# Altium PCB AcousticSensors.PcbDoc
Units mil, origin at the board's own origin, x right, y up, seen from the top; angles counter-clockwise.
Board outline 6000 x 4000 mil, 2 copper layers (Top Layer, Bottom Layer); 17 components, 11 nets, 41 pads, 10 vias.
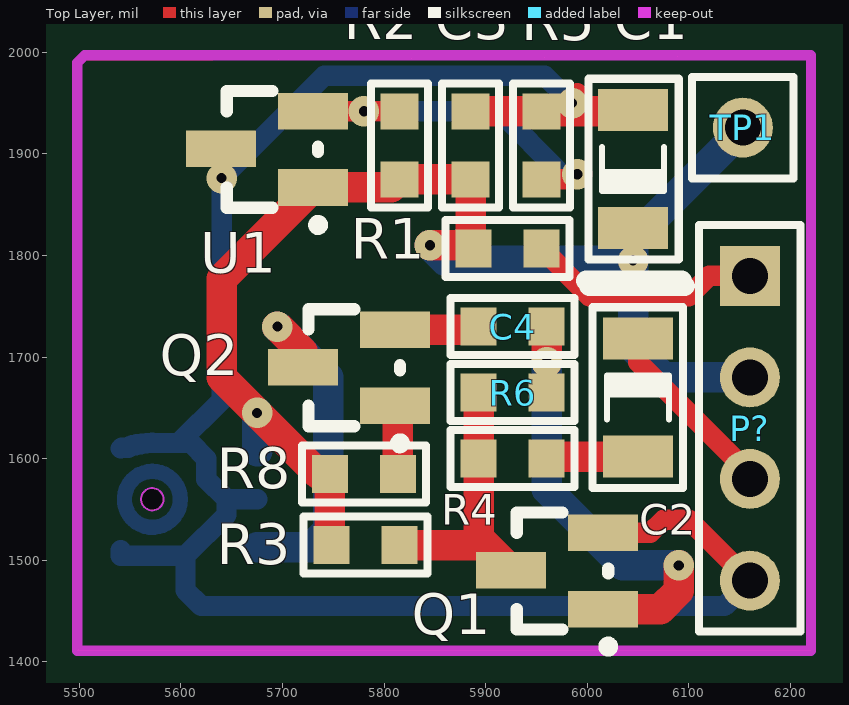
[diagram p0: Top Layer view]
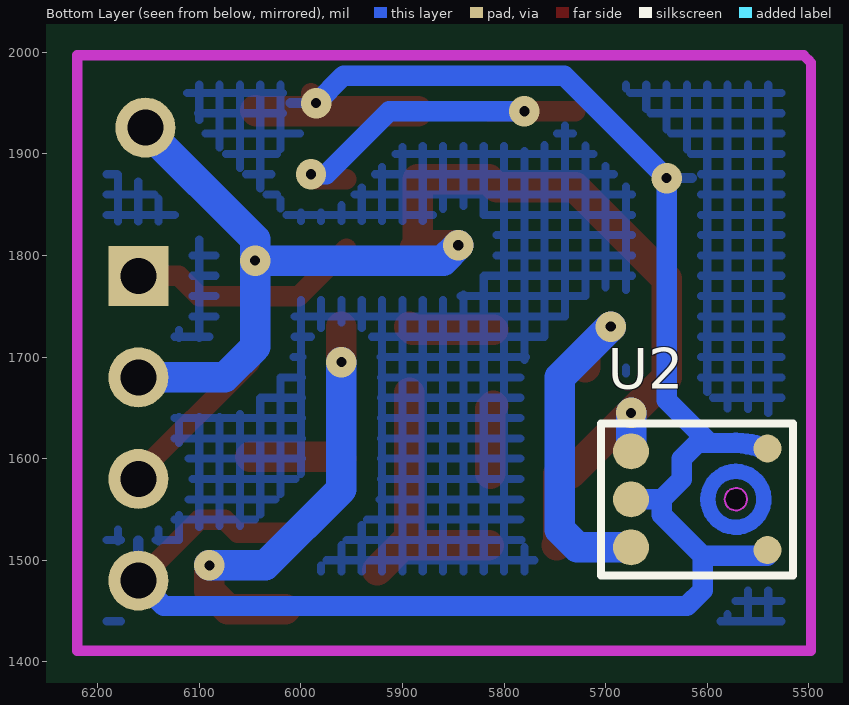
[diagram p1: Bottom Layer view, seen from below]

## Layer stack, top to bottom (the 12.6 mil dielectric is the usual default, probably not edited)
Top Solder: solder mask 0.4, Solder Resist, Dk 3.5
Top Layer: signal copper 1.4
Dielectric 1: dielectric 12.6, FR-4, Dk 4.8
Bottom Layer: signal copper 1.4
Bottom Solder: solder mask 0.4, Solder Resist, Dk 3.5

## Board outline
1000,1000 7000,1000 7000,5000 1000,5000
cut-out: 5571.81,1549.05 cw(c5571.81,1560.07) 5560.78,1560.07 cw(c5571.81,1560.07) 5571.81,1571.1 cw(c5571.81,1560.07) 5582.83,1560.07 cw(c5571.81,1560.07)

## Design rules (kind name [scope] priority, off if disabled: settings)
Clearance [All] p1: gap=20
PolygonConnect [All] p1: connectstyle=Relief reliefconductorwidth=10 reliefentries=4 polygonreliefangle="90 Angle" airgapwidth=10
RoutingVias [All] p1: holewidth=28 width=50 viastyle="Through Hole" minholewidth=5 minwidth=10 maxholewidth=50 maxwidth=50
SolderMaskExpansion [All] p1: expansion=4
Width [All] p1: maxlimit=100 minlimit=10 preferedwidth=30
30 further rules are at their usual default settings.

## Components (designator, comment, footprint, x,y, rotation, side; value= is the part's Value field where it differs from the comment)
C1 "1uF/1206" TAN_A 6045,1885 r270 top
C2 "1uF/1206" TAN_A 6050,1660 r90 top
C3 "0.1uF/0603" C0603 5885,1908.46 r270 top
C4 "0.1uF/0603" C0603 5926.54,1730 r0 top
P? "Header 4" HDR1X4 6160,1780 r270 top
Q1 "MMBT3904" SOT-23 5970.28,1489.5 r90 top
Q2 "MMBT3904" SOT-23 5765.28,1689.5 r90 top
R1 "100ohm/0805" R0603 5921.54,1806.93 r0 top
R2 "10K/1%/0603" R0603 5815,1908.46 r90 top
R3 "10K/0603" R0603 5781.54,1515 r0 top
R4 "0 ohm/0603" R0603 5926.54,1600 r180 top
R5 "51K/1%/0603" R0603 5955,1908.46 r90 top
R6 "220K/0603" R0603 5926.54,1665 r0 top
R8 "20K/0603" R0603 5780,1585 r180 top
TP1 "REF" TP 6155,1925 r0 top
U1 "TL431BCDBZR" SOT-23 5684.72,1904.43 r90 top
U2 "INMP411" INMP411 5675,1512.76 r0 bottom

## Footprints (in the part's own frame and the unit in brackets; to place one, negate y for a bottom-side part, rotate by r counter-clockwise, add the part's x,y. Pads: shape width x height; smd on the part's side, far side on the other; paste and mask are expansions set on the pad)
C0603 [mm]
  rect 0.9x0.95 smd: 1(0.85,0) 2(-0.85,0)
  silkscreen extent -1.55,-0.71 1.55,0.71, body extent -0.85,-0.45 0.85,0.45, height 0.45
HDR1X4 [mm] "Connector; Header; 4 Position"
  rect 1.5x1.5 hole 0.9: 1(0,0)
  round 1.5 hole 0.9: 2(2.54,0) 3(5.08,0) 4(7.62,0)
  silkscreen extent -1.27,-1.27 8.89,1.27
INMP411 [mm]
  round 0.9 smd: 1(0,0) 5(0,-2.4) 6(0,-1.2)
  round 0.7 smd mask+0.09: 2(-3.41,0.07)
  round 0.7 smd mask+0.08: 4(-3.41,-2.47)
  Top Layer lines w0.381: -2.62,-1.9 cw(c-2.62,-1.2) -1.92,-1.2 cw(c-2.62,-1.2) -2.62,-1.9
  silkscreen extent -4.05,-3.1 0.75,0.7
R0603 [mm]
  rect 0.9x0.95 smd: 1(0.85,0) 2(-0.85,0)
  silkscreen extent -1.55,-0.71 1.55,0.71, body extent -0.85,-0.45 0.85,0.45, height 0.45
SOT-23 [mil]
  rect 36x68.9 smd: 1(-37.5,-45.28) 2(37.5,-45.28) 3(0.5,45.28)
  silkscreen extent -79,-55 58,40, body extent -58,-35 60,20, height 47
TAN_A [mm]
  rect 1.05x1.75 smd: 1(1.475,0) 2(-1.475,0)
  silkscreen extent -2.26,-1.17 2.79,1.22, body extent -1.6,-0.85 1.6,0.85, height 0.55
TP [mm]
  round 1.5 hole 0.9: 1(-0.05,0.021)
  silkscreen extent -1.32,-1.25 1.22,1.29

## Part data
C1 C2 C3 C4: library part C
P?: "Header, 4-Pin"
Q1 Q2: "NPN Transistor"
R1 R2 R3 R4 R5 R6 R8: library part RES
TP1: library part Testpoint
U1: library part TL431CDBZR, "CAN NOT BE MFDT or MSDT"

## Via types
v1: diameter 30, hole 10, Top Layer to Bottom Layer, 10 vias

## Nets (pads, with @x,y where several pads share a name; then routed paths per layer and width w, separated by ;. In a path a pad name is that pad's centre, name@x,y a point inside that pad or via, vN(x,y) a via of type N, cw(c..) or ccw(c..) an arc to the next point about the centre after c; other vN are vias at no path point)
5V: P?.1 R1.1 | length 232.7
  Top Layer w20: R1.1 6001.93,1760 6100,1760 6120,1780 P?.1
GND: C1.2 C3.2 P?.4 Q1.2 R5.1 U1.3 U2.2 U2.4 U2.6 | length 1955.5
  Top Layer w20: v1(5985,1950) 5985,1955 5990,1960 v1@5990,1941.93 ; Q1.2 6062,1527 6075,1540 6100,1540 P?.4
  Top Layer w30: C3.2 R5.1 v1@5985,1941.93 ; v1@5990,1941.93 6043.86,1941.93 C1.2
  Bottom Layer w20: U2.2 5540.75,1504.4 5604.4,1504.4 ; U2.4 5541.42,1610.67 5548.14,1610.67 5549.59,1612.11 5550.94,1612.11 5552.05,1613.22 5555.45,1613.22 5556.48,1614.25 5560.59,1614.25 5561.12,1614.78 5561.32,1614.78 5561.54,1615 5565.68,1615 5566.14,1615.45 5571.7,1615.45 5571.85,1615.6 5597.89,1615.45 ; U2.6 5644.87,1560 ; v1(5985,1950) 5958.07,1976.93 5740.83,1976.93 v1(5640,1876.1) 5640,1657.56 5597.89,1615.45 ; P?.4 6135,1455 5620,1455 5604.4,1470.6 5604.4,1504.4 ; 5597.89,1615.45 5609.55,1615.45 5625,1600 5625,1579.87 5644.87,1560 ; 5604.4,1504.4 5644.87,1544.87 5644.87,1560
MICIN: C2.1 P?.3 | length 183.6
  Top Layer w20: C2.1 6050,1695 6160,1585 P?.3
NetC2_2: C2.2 R4.2 | length 90.8
  Top Layer w30: R4.2 5961.93,1601.93 C2.2
NetC4_1: C4.1 Q1.1 R6.1 | length 428
  Top Layer w30: v1(5960,1695) C4.1 ; Q1.1 6072,1452 6090,1470 v1(6090,1495)
  Bottom Layer w30: v1(5960,1695) 5960,1570 6035,1495 v1(6090,1495)
NetC4_2: C4.2 Q2.2 | length 83.8
  Top Layer w30: Q2.2 5890.07,1727 C4.2
NetQ1_3: Q1.3 R3.1 R4.1 R6.2 | length 273.2
  Top Layer w30: R3.1 5900,1515 ; R6.2 R4.1 5893.07,1521.93 5900,1515 ; Q1.3 5900,1515
NetQ2_1: Q2.1 R8.2 | length 68.2
  Top Layer w30: Q2.1 5813.46,1649.09 R8.2
NetQ2_3: Q2.3 U2.1 | length 348.2
  Top Layer w30: v1(5695,1730) 5720,1705 Q2.3
  Bottom Layer w30: U2.1 5727.76,1512.76 5745,1530 5745,1680 v1(5695,1730)
NetR2_1: R2.1 R5.2 U1.2 | length 357.7
  Top Layer w20: U1.2 v1(5780,1941.93) R2.1 ; R5.2 5985,1875 v1(5990,1880)
  Bottom Layer w20: v1(5780,1941.93) 5913.07,1941.93 5975,1880 v1(5990,1880)
REF: C1.1 C3.1 P?.2 R1.2 R2.2 R3.2 R8.1 TP1.1 U1.1 U2.5 | length 1340.4
  Top Layer w30: R3.2 5746.54,1516.54 R8.1 5735,1585 v1(5675,1645) 5640,1680 5640,1776.93 U1.1 5806.93,1866.93 R2.2 C3.1 R1.2@5885,1810 ; v1(5845,1810) R1.2@5885,1810 ; R1.2 R1.2@5885,1810
  Bottom Layer w30: U2.5 v1(5675,1645) ; v1(5845,1810) 5860,1795 v1(6045,1795) ; TP1.1 6153.02,1924.02 6045,1816 v1(6045,1795) ; P?.2 6075,1680 6045,1710 v1(6045,1795)

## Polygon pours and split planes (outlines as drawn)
GND on Top Layer "Keep-Out Layer-No Net" (hatched 90Degree grid 20 track 8, pour order 0): 6220,1997 6220,1411 5498,1411 5499.75,1412.75 5499.75,1991.75
GND on Bottom Layer "Keep-Out Layer-No Net" (hatched 90Degree grid 20 track 8, pour order 2): 6220,1997 6220,1411 5498,1411 5498,1990 5503.25,1995.25 5505,1997

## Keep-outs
Keep-Out Layer:
  circle w1.97: c5571.81,1560.07 r11.02
  lines w10: 5498,1411 6220,1411 6220,1990 6220,1997 5505,1997 5503.25,1995.25 5499.75,1991.75 5498,1990 5498,1411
